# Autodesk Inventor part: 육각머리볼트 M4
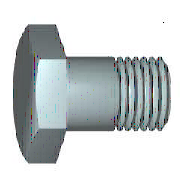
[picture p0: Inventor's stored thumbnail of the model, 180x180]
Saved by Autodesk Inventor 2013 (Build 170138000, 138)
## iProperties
IsCustomPart: 1
Created: 2012-02
Part Number: 육각머리볼트 M4
Material: 스테인리스강
Description: 6각 머리 볼트 및 6각 머리 나사
Document SubType Name: Modeling
Standard: KS B 1002
Designer: mduedu
Standards Organization: KS
Language: ko-KR
Size Designation: A + B M4 x 10
Categories: <MemberInstance><Categories><Category DisplayName="조임쇠" InternalName="e4da775c-781d-43d5-af7c-5136215cf5a6" Mnemonic="FSTN"><Category DisplayName="볼트" InternalN
Density: 8.08 g/cm^3
Mass: 1.91435 g
Surface Area: 2.70732 cm^2
Volume: 0.236925 cm^3
Author: mduedu
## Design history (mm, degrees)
sketch "스케치1"
  geometry: L1 (0, 2.94)-(0, 2); L2 (2.1, 2)-(10, 2); L3 (10, 2)-(10, 0); L4 (10, 0)-(-0.4, 0); L5 (-2.48, 0)-(12.08, 0) reference; L6 (-0.4, 0)-(-0.4, 2.94); L7 (-0.4, 2.94)-(0, 2.94); L8 (2.1, 2)-(1.67, 2); L9 (1.67, 2)-(0, 2); L10 (0, -0.588)-(0, 3.528) reference
  constraints: 16 end point, 2 collinear, 2 perpendicular, 1 parallel
  dimensions: "d0" = 10 distance between parallel lines of L3 L1 (= NLG); "d1" = 7.9 distance from line of L2.start L3 (= GEL); "d2" = 4 diameter of L2 L4 (= GD); "d9" = 0.4001 distance between parallel lines of L6 L1 (computed from SD); "d10" = 5.88 diameter of L7 L4 (= SD2); "d13" = 0.42952 distance of L2.start L8.end (computed from GAL); "d14" = 4 diameter of L9 L4 (= BDM)
revolve "본체" sketch "스케치1" stored, may be unused: angle "d12" = 90 deg
sketch "스케치2"
  geometry: L1 (0, 4.041)-(3.5, 2.021); L2 (3.5, 2.021)-(3.5, -2.021); L3 (3.5, -2.021)-(0, -4.041); L4 (0, -4.041)-(-3.5, -2.021); L5 (-3.5, -2.021)-(-3.5, 2.021); L6 (-3.5, 2.021)-(0, 4.041); 2 further points
  constraints: 12 end point, 1 coincident, 1 vertical, 11 other
  dimensions: "d11" = 7 distance between parallel lines of L5 L2 (= SW)
extrude "머리" join sketch "스케치2" distance "d3" = 2.4 (= KOH - SD); taper "d4" = 0 deg
sketch "스케치4"
  geometry: L1 (-2.8, 3.5)-(-2.8, 4.041); L2 (-2.8, 4.041)-(-2.487, 4.041); L3 (-2.487, 4.041)-(-2.8, 3.5); L4 (-3.28, 0)-(0.08, 0) reference; L5 (-0.4, 4.041)-(-2.8, 4.041) reference; L6 (-2.8, 2.021)-(-2.8, 4.041) reference
  constraints: 6 end point, 2 collinear, 1 perpendicular, 1 vertical
  dimensions: "d5" = 30 deg angle of L3 L1 (= ANG1); "d19" = 7 diameter of L1.start L4 (= SW0)
revolve "모따기1" sketch "스케치4" stored, may be unused: angle "d21" = 90 deg
workplane "Work Plane1"
body "Solid1"
feature "스레드" dims "d15" = 7.9 (= GEL), "d16" = 0
chamfer "모따기2" distance "d6" = 0.42941 (= -0.5 x SPD + 0.5 x GD); stored, may be unused: second distance "d7" = 0.42952 (computed from GUL), angle "d55" = 45 deg
other parameters: "NLG" = 10 [user parameter; used in 1 equation term], "GD" = 4 (= NND) [user parameter; used in 2 equation terms], "BDM" = 4 (= NND) [user parameter; used in 1 equation term], "KOH" = 2.8 [user parameter; used in 1 equation term], "GEL" = 7.9 [user parameter; used in 2 equation terms], "SW" = 7 [user parameter; used in 3 equation terms], "SW0" = 7 (= SW) [user parameter; used in 1 equation term], "SPD" = 3.14117 (= NND - 1.2269 x PTC) [user parameter; used in 1 equation term], "SD2" = 5.88 (= SDH) [user parameter; used in 1 equation term], "SD" = 0.4 [user parameter; used in 2 equation terms], "ANG1" = 30 deg [user parameter; used in 1 equation term], "GAL" = 0.42941 (= 0.61345 x PTC) [user parameter; used in 1 equation term], "GUL" = 0.42941 (= 0.61345 x PTC) [user parameter; used in 1 equation term], "d8" = 0, "RR" = 0.2 [user parameter], "d57" = 0, "d58" = 0, "TPU" = 14.28571 (computed from PTC) [user parameter], "GD1" = 3.14117 (= THREADDIA - 1.2269 x PTC) [user parameter], "THREADDIA" = 4 [user parameter; used in 1 equation term], "SDH" = 5.88 [user parameter; used in 1 equation term], "SDHG" = 2.1 [user parameter], "TOA" = 30 deg [user parameter], "PTC" = 0.7 [user parameter; used in 5 equation terms], "NND" = 4 [user parameter; used in 3 equation terms], "E0" = 8.085 (= 1.155 x SW) [user parameter]
